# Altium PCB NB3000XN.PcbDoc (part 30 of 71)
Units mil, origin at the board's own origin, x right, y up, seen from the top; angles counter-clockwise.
Board outline 9527.56 x 6929.77 mil, 6 copper layers (Top Layer, GND+SHIELD, MidLayer1, MidLayer2, P2 - 3V3+5V0, Bottom Layer), stack 62.375 mil thick; 832 components, 1027 nets, 4655 pads, 4981 vias.
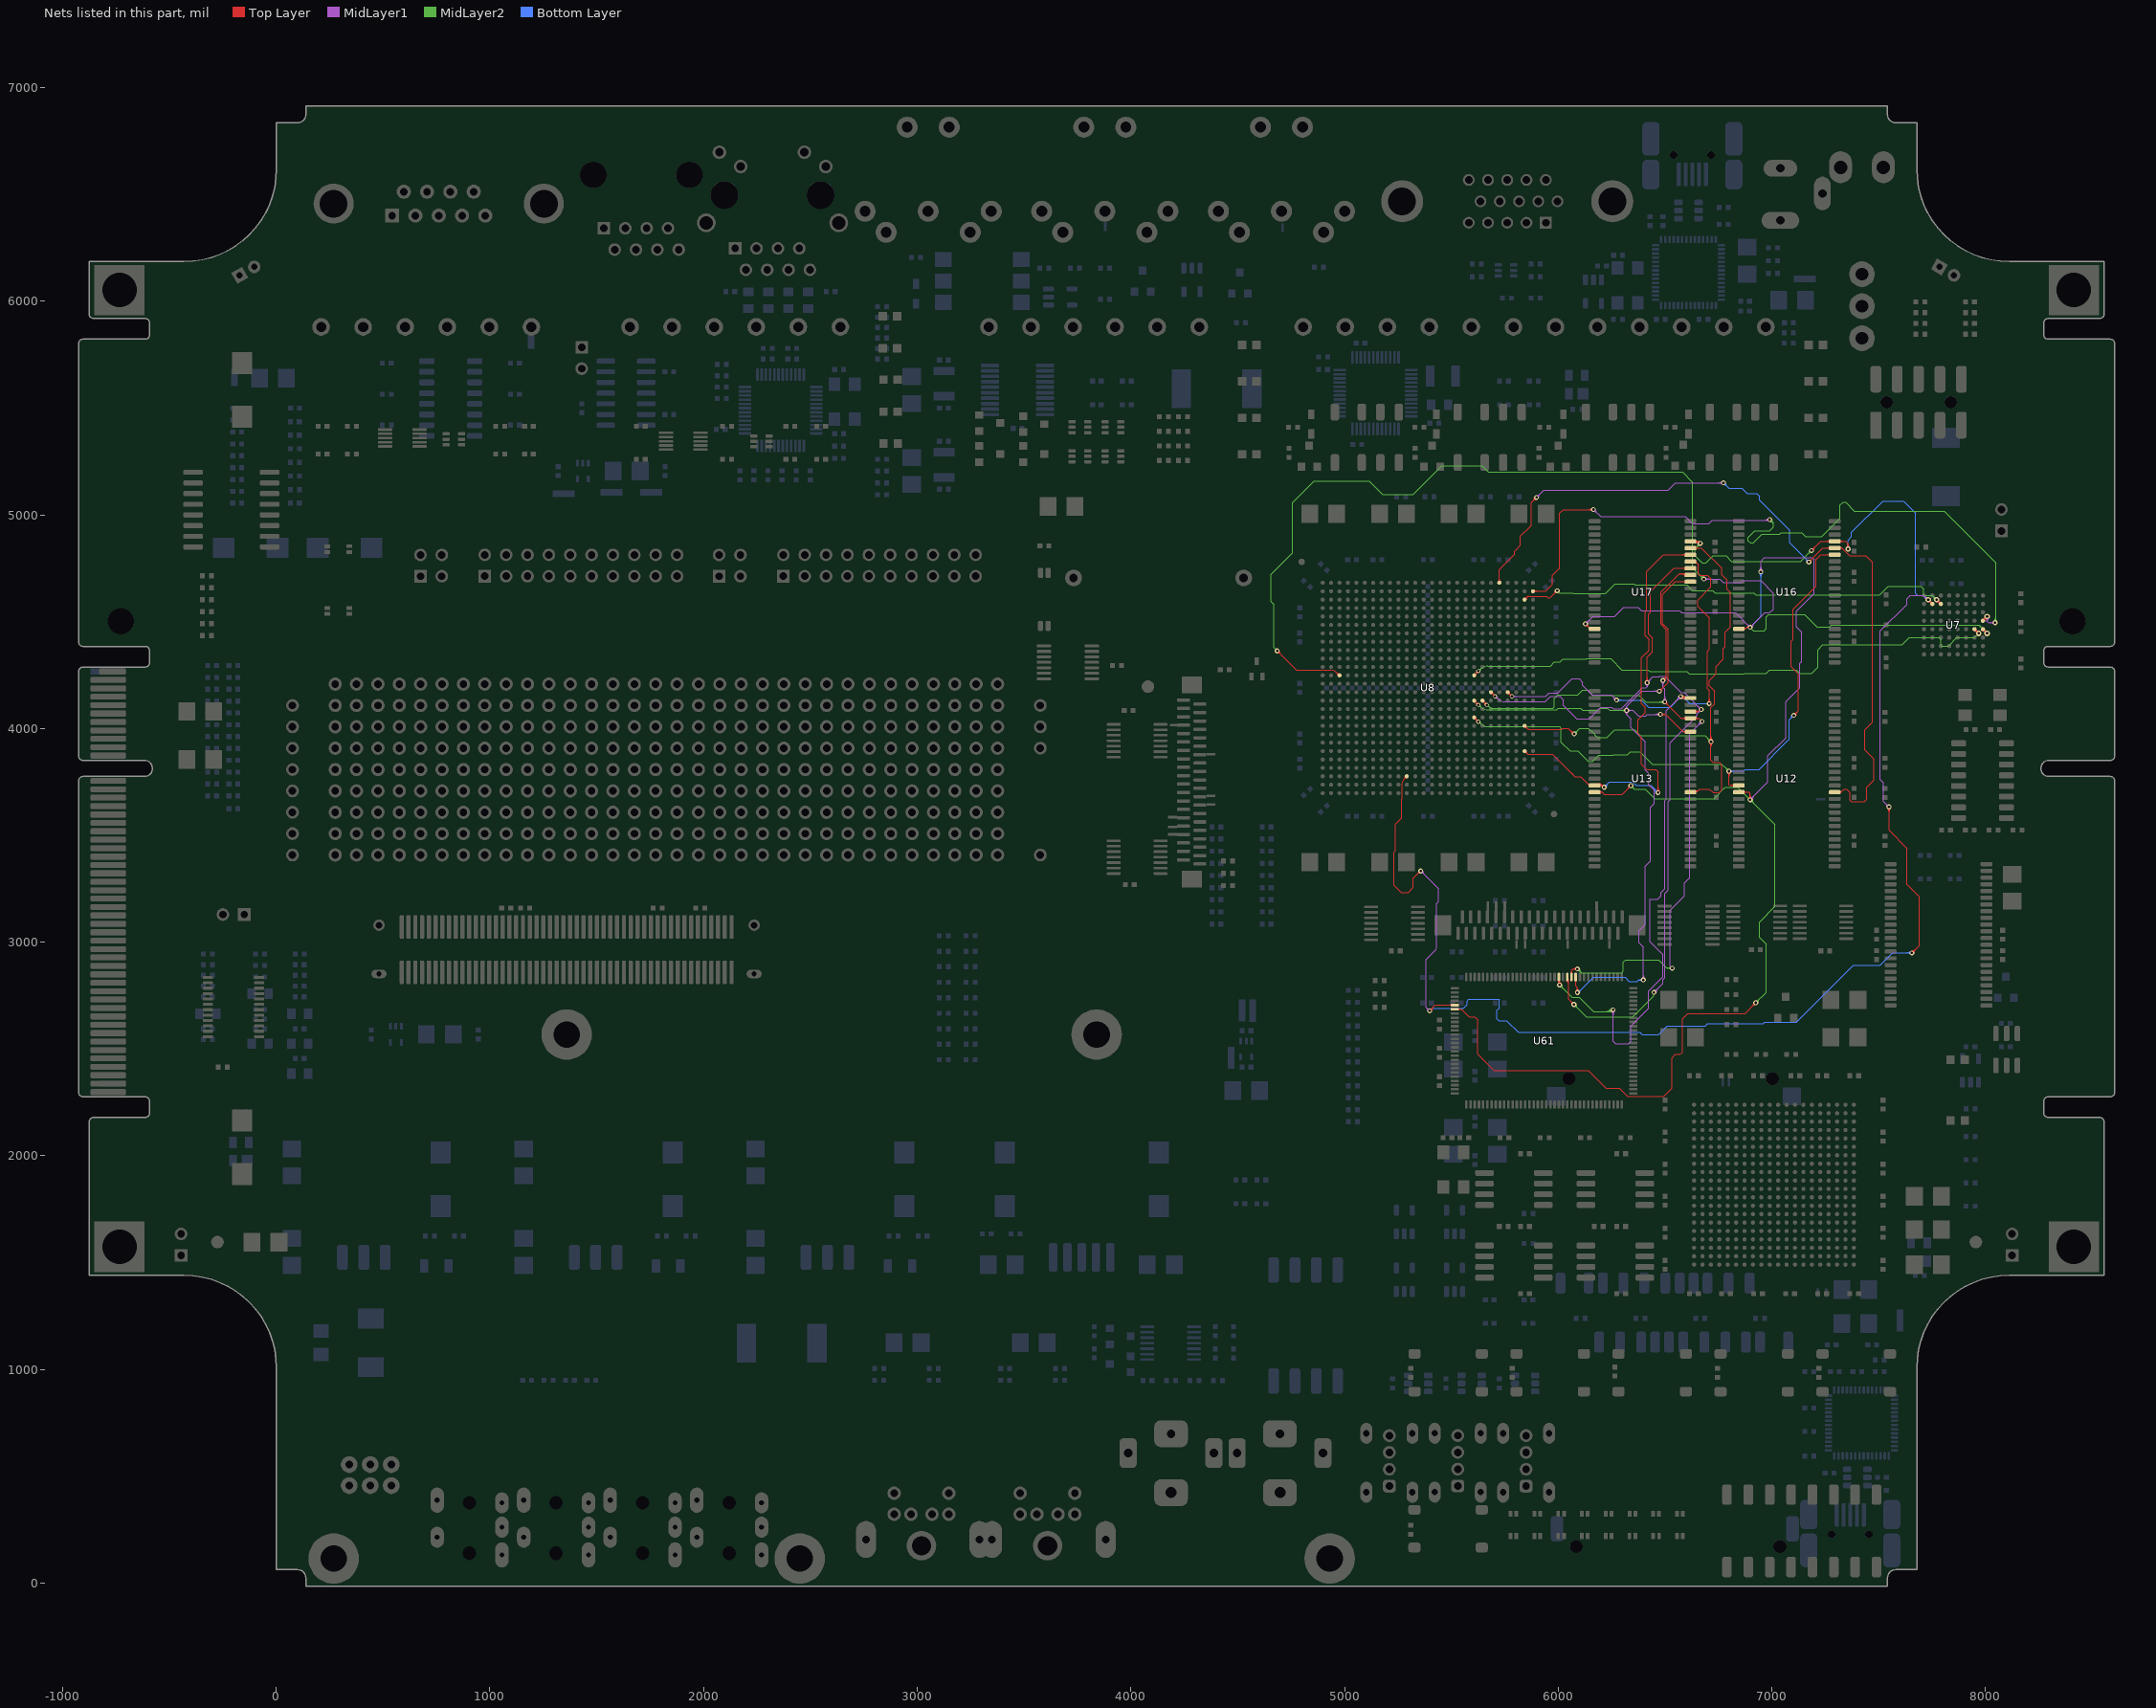
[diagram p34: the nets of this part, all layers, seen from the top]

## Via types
v1: diameter 23, hole 11.81, Top Layer to Bottom Layer, 3672 vias
v2: diameter 26, hole 11.81, Top Layer to Bottom Layer, 461 vias
v3: diameter 19, hole 11.81, Top Layer to Bottom Layer, tented both sides, 396 vias
v4: diameter 23.62, hole 11.81, Top Layer to Bottom Layer, 288 vias
v5: diameter 20, hole 11.81, Top Layer to Bottom Layer, 91 vias
v6: diameter 23, hole 11.81, Top Layer to Bottom Layer, tented both sides, 50 vias
v7: diameter 31, hole 11.81, Top Layer to Bottom Layer, 15 vias
v8: diameter 27.56, hole 11.81, Top Layer to Bottom Layer, tented both sides, 4 vias
v9: diameter 29, hole 11.81, Top Layer to Bottom Layer, 3 vias
v10: diameter 21, hole 11.81, Top Layer to Bottom Layer, 1 vias

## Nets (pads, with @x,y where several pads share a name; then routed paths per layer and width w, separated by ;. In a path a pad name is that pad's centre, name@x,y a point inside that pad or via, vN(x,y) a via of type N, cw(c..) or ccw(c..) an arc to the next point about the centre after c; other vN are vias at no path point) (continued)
DB_MEM.BUS_D28: U8.R19 U13.48 U17.35 U61.76 | length 4548
  Top Layer w4: U8.R19@5606.54,4123.44 cw(c5606.54,4105.34) 5619.34,4118.14 cw(c5632.14,4130.94) U8.R19@5614.04,4130.94 ; U8.R19@5606.54,4123.6 cw(c5606.54,4105.88) 5619.07,4118.41 cw(c5631.6,4130.94) U8.R19@5613.88,4130.94 ; U8.R19@5606.54,4130.94 v3(5626.22,4111.26) ; U61.76@6078.98,2821.32 cw(c6072.15,2814.49) 6081.81,2814.49 cw(c6091.47,2814.49) U61.76@6084.64,2821.32 ; U61.76@6081.81,2837.34 6081.81,2795 6090.19,2786.62 ; v1@6083.7,2771.64 ccw(c6069.67,2786.62) 6090.19,2786.62 ; v1@6086.43,2768.72 ccw(c6078.31,2777.39) 6090.19,2777.39 ccw(c6102.07,2777.39) v1@6093.95,2768.72 ; v1(6090.19,2764.71) 6090.19,2786.62 ; v1@6096.68,2771.64 cw(c6110.71,2786.62) 6090.19,2786.62 ; v1(6473.52,4175.04) 6515.19,4216.71 6515.19,4465.37 6488.86,4491.71 6488.86,4627.58 6548.52,4687.24 U17.35@6619.41,4687.24 ; v1@6473.52,4180.54 ccw(c6473.52,4193.82) 6482.91,4184.43 ccw(c6492.3,4175.04) v1@6479.02,4175.04 ; v1@6473.52,4184.54 ccw(c6473.52,4207.48) 6489.74,4191.26 ccw(c6505.96,4175.04) v1@6483.02,4175.04 ; v1(6478.52,4066.71) 6503.29,4066.71 6584.53,3985.47 ; v1@6482.41,4062.82 cw(c6491.8,4053.43) 6491.8,4066.71 cw(c6491.8,4079.99) v1@6482.41,4070.6 ; v1@6485.24,4059.99 cw(c6501.46,4043.77) 6501.46,4066.71 cw(c6501.46,4089.64) v1@6485.24,4073.43 ; U13.48@6595.76,3980.29 ccw(c6584.53,3970.72) 6584.53,3985.47 ; U13.48@6595.76,3990.66 cw(c6584.53,4000.23) 6584.53,3985.47 ; U17.35@6596.19,4681.59 ccw(c6582.54,4667.93) 6582.54,4687.24 ccw(c6582.54,4706.56) U17.35@6596.19,4692.9 ; U13.48@6619.41,3985.47 6584.53,3985.47 ; 5613.42,4124.06 cw(c5600.61,4111.26) 5618.72,4111.26 ccw(c5600.61,4111.26) 5613.42,4124.06 ; 5613.42,4124.06 ccw(c5626.22,4136.87) 5626.22,4118.76 cw(c5626.22,4136.87) 5613.42,4124.06
  MidLayer1 w4: v4@6314,4077.24 cw(c6304.52,4065) 6320,4065 ; v4@6314.24,4092.94 ccw(c6306.04,4104.24) 6320,4104.24 ; v4@6316.44,4080.4 cw(c6310.83,4073.15) 6320,4073.15 cw(c6329.17,4073.15) v4@6323.56,4080.4 ; v4@6324.11,4080.89 cw(c6334.03,4070.97) 6334.03,4085 cw(c6334.03,4099.03) v4@6324.11,4089.11 ; v4@6325.76,4092.94 cw(c6333.96,4104.24) 6320,4104.24 ; v4@6326,4077.24 ccw(c6335.48,4065) 6320,4065 ; v4@6326.94,4078.06 cw(c6343.69,4061.31) 6343.69,4085 cw(c6343.69,4108.69) v4@6326.94,4091.94 ; v1@6391.81,2830.09 ccw(c6375.59,2846.31) 6398.52,2846.31 ccw(c6421.46,2846.31) v1@6405.24,2830.09 ; v1@6394.64,2827.26 ccw(c6385.25,2836.65) 6398.52,2836.65 ccw(c6411.8,2836.65) v1@6402.41,2827.26 ; v1(6398.52,2823.37) 6398.52,2978.02 6379.19,2997.35 6379.19,3054.08 6406.86,3081.75 6406.86,3356.39 6431.86,3381.39 6431.86,3631.06 6449.19,3648.39 6449.19,3711.35 6423.52,3737.02 6423.52,3789.35 6406.86,3806.02 6406.86,3937.69 6340,4004.54 6340,4045 6320,4065 ; v1@6466.81,4168.32 ccw(c6450.59,4152.11) 6450.59,4175.04 ccw(c6450.59,4197.98) v1@6466.81,4181.76 ; v1@6469.64,4171.15 ccw(c6460.25,4161.76) 6460.25,4175.04 ccw(c6460.25,4188.32) v1@6469.64,4178.93 ; v1@6471.81,4059.99 ccw(c6455.59,4043.77) 6455.59,4066.71 ccw(c6455.59,4089.64) v1@6471.81,4073.43 ; v1(6473.52,4175.04) 6390.8,4175.04 6320,4104.24 ; v1@6474.64,4062.82 ccw(c6465.25,4053.43) 6465.25,4066.71 ccw(c6465.25,4079.99) v1@6474.64,4070.6 ; v1(6478.52,4066.71) 6416.71,4066.71 6410,4060 6375,4060 6350,4085 v4(6320,4085) ; 6320,4065 v4(6320,4085) ; v4(6320,4085) 6320,4104.24
  MidLayer2 w4: v3@5626.87,4103.79 cw(c5628.45,4085.75) 5640.09,4099.62 ; v3@5633.69,4111.91 ccw(c5651.73,4113.49) 5640.09,4099.62 ; v4@6313.06,4078.06 ccw(c6296.31,4061.31) 6296.31,4085 ccw(c6296.31,4108.69) v4@6313.06,4091.94 ; v4@6315.89,4080.89 ccw(c6305.97,4070.97) 6305.97,4085 ccw(c6305.97,4099.03) v4@6315.89,4089.11 ; v4(6320,4085) 6242.25,4085 6231.54,4095.71 6195.71,4095.71 6185,4085 6115,4085 6105,4095 6000,4095 5992.4,4087.4 5920,4087.4 5910,4087.4 5782.64,4087.4 5763.22,4087.4 5689.1,4087.4 5669.6,4087.4 cw(c5669.6,4129.13) 5640.09,4099.62
  Bottom Layer w4: v1(6090.19,2764.71) 6094.86,2764.71 6166.19,2836.04 6312.52,2836.04 6331.86,2816.71 6370,2816.71 6376.67,2823.37 ; v1@6090.19,2766.21 ccw(c6090.19,2781.1) 6100.72,2770.57 ; v1@6090.19,2770.21 ccw(c6090.19,2794.75) 6107.55,2777.4 ; v1@6090.19,2774.21 ccw(c6090.19,2808.41) 6114.37,2784.23 ; v1@6099.69,2764.71 cw(c6111.36,2764.71) 6103.11,2772.96 ; v1@6391.58,2816.89 ccw(c6376.67,2802.98) 6376.67,2823.37 ; v1@6391.58,2829.86 cw(c6376.67,2843.77) 6376.67,2823.37 ; v1@6394.5,2819.62 ccw(c6385.87,2811.57) 6385.87,2823.37 ccw(c6385.87,2835.18) v1@6394.5,2827.13 ; v1(6398.52,2823.37) 6376.67,2823.37
DB_MEM.BUS_D29: U8.R20 U13.50 U17.36 U61.77 | length 4450
  Top Layer w4: U8.R20@5645.91,4123.44 cw(c5645.91,4105.34) 5658.71,4118.14 cw(c5671.51,4130.94) U8.R20@5653.41,4130.94 ; U8.R20@5645.91,4123.6 cw(c5645.91,4105.88) 5658.44,4118.41 cw(c5670.97,4130.94) U8.R20@5653.25,4130.94 ; U8.R20@5645.91,4130.94 v3(5665.59,4111.26) ; U61.77@6059.3,2853.36 ccw(c6052.47,2860.19) 6062.13,2860.19 ccw(c6071.78,2860.19) U61.77@6064.95,2853.36 ; U61.77@6062.12,2837.34 6062.13,2867.04 6070.13,2875.04 ; v1@6082.84,2869.02 ccw(c6070.13,2858.6) 6070.13,2875.04 ; v1@6082.84,2881.06 cw(c6070.13,2891.48) 6070.13,2875.04 ; v1@6085.94,2871.56 ccw(c6078.57,2865.52) 6078.57,2875.04 ccw(c6078.57,2884.56) v1@6085.94,2878.53 ; v1(6090.19,2875.04) 6070.13,2875.04 ; v1(6490.19,4225.04) 6506.86,4241.71 6506.86,4462.39 6480.52,4488.73 6480.52,4639.37 6566.19,4725.04 6601.84,4725.04 6601.84,4718.74 U17.36@6619.41,4718.74 ; v1@6490.19,4230.54 ccw(c6490.19,4243.82) 6499.58,4234.43 ccw(c6508.97,4225.04) v1@6495.69,4225.04 ; v1@6490.19,4234.54 ccw(c6490.19,4257.48) 6506.41,4241.26 ccw(c6522.63,4225.04) v1@6499.69,4225.04 ; v1@6498.52,4115.54 cw(c6498.52,4092.61) 6514.74,4108.82 cw(c6530.96,4125.04) v1@6508.02,4125.04 ; v1@6498.52,4119.54 cw(c6498.52,4106.26) 6507.91,4115.65 cw(c6517.3,4125.04) v1@6504.02,4125.04 ; v1(6498.52,4125.04) 6575.1,4048.46 U13.50@6619.41,4048.46 6658.44,4048.46 v1(6673.52,4033.37) ; 6567.33,4725.04 cw(c6567.33,4684.21) U17.36@6596.19,4713.08 ; 6576.98,4725.04 cw(c6576.98,4693.87) U17.36@6599.02,4715.91 ; 6586.64,4725.04 cw(c6586.64,4703.53) U17.36@6601.85,4718.74 ; U13.50@6596.19,4042.81 ccw(c6582.54,4029.15) 6582.54,4048.46 ccw(c6582.54,4067.78) U13.50@6596.19,4054.12 ; U13.50@6642.63,4042.81 cw(c6656.28,4029.15) 6656.28,4048.46 cw(c6656.28,4067.78) U13.50@6642.63,4054.12 ; 5652.79,4124.06 cw(c5639.98,4111.26) 5658.09,4111.26 ccw(c5639.98,4111.26) 5652.79,4124.06 ; 5652.79,4124.06 ccw(c5665.59,4136.87) 5665.59,4118.76 cw(c5665.59,4136.87) 5652.79,4124.06
  MidLayer1 w4: v1@6483.47,4218.32 cw(c6467.26,4202.11) 6490.19,4202.11 cw(c6513.13,4202.11) v1@6496.91,4218.32 ; v1@6486.3,4221.15 cw(c6476.91,4211.76) 6490.19,4211.76 cw(c6503.47,4211.76) v1@6494.08,4221.15 ; v1(6490.19,4225.04) 6490.19,4193.33 6498.52,4185 v1(6498.52,4125.04) ; v1@6491.81,4131.76 ccw(c6475.59,4147.98) 6498.52,4147.98 ccw(c6521.46,4147.98) v1@6505.24,4131.76 ; v1@6494.64,4128.93 ccw(c6485.25,4138.32) 6498.52,4138.32 ccw(c6511.8,4138.32) v1@6502.41,4128.93 ; v1(6533.86,2878.37) 6523.52,2888.71 6523.52,3150.04 6590.19,3216.71 6590.19,3277.04 6615.19,3302.04 6615.19,3975.04 v1(6673.52,4033.37) ; v1@6664.02,4033.37 cw(c6641.09,4033.37) 6657.31,4017.16 cw(c6673.52,4000.94) v1@6673.52,4023.87 ; v1@6668.02,4033.37 cw(c6654.75,4033.37) 6664.14,4023.99 cw(c6673.52,4014.6) v1@6673.52,4027.87
  MidLayer2 w4: v3@5666.24,4103.79 cw(c5667.82,4085.75) 5679.46,4099.62 cw(c5691.1,4113.49) v3@5673.06,4111.91 ; 5679.17,4099.87 ccw(c5689.1,4109.8) 5689.1,4095.75 5782.64,4095.75 5910,4095.75 5920,4095.75 5975.75,4095.75 5981.86,4101.86 5981.86,4141.71 5998.52,4158.37 6092.54,4158.37 6114.17,4180 6139.56,4180 6163.19,4156.37 6320,4156.37 6378.54,4156.37 6409.88,4125.04 v1(6498.52,4125.04) ; v1@6090.19,2865.54 cw(c6090.19,2842.61) 6106.41,2858.82 cw(c6122.63,2875.04) v1@6099.69,2875.04 ; v1@6090.19,2869.54 cw(c6090.19,2856.26) 6099.58,2865.65 cw(c6108.97,2875.04) v1@6095.69,2875.04 ; v1@6090.23,2875 v1(6090.19,2875.04) 6107.86,2857.37 6297,2857.37 6305,2865.37 6305,2907.71 6315,2917.71 6470,2917.71 6509.33,2878.37 v1(6533.86,2878.37) ; v1@6491.81,4118.32 ccw(c6475.59,4102.11) 6475.59,4125.04 ccw(c6475.59,4147.98) v1@6491.81,4131.76 ; v1@6494.64,4121.15 ccw(c6485.25,4111.76) 6485.25,4125.04 ccw(c6485.25,4138.32) v1@6494.64,4128.93 ; v1@6527.14,2871.66 ccw(c6510.92,2855.44) 6510.92,2878.37 ccw(c6510.92,2901.31) v1@6527.14,2885.09 ; v1@6529.97,2874.49 ccw(c6520.58,2865.1) 6520.58,2878.37 ccw(c6520.58,2891.65) v1@6529.97,2882.26
DB_MEM.BUS_D30: U8.P21 U13.51 U17.37 U61.78 | length 4758.4
  Top Layer w4: U8.P21@5685.28,4162.81 cw(c5685.28,4144.71) 5698.08,4157.51 cw(c5710.88,4170.31) U8.P21@5692.78,4170.31 ; U8.P21@5685.28,4162.97 cw(c5685.28,4145.25) 5697.81,4157.78 cw(c5710.34,4170.31) U8.P21@5692.62,4170.31 ; U8.P21@5685.28,4170.31 v3(5704.96,4150.63) ; U61.78@6039.61,2821.32 cw(c6018.09,2799.8) 6048.52,2799.8 ; U61.78@6042.44,2824.14 cw(c6027.75,2809.46) 6048.52,2809.46 ; U61.78@6045.27,2826.97 cw(c6037.41,2819.11) 6048.52,2819.11 ; U61.78@6048.1,2829.8 cw(c6047.07,2828.77) 6048.52,2828.77 ; 6048.52,2827.29 6048.52,2733.37 v1(6073.52,2708.37) ; v1@6064.02,2708.37 ccw(c6041.09,2708.37) 6057.31,2724.59 ccw(c6073.52,2740.81) v1@6073.52,2717.87 ; v1@6068.02,2708.37 ccw(c6054.75,2708.37) 6064.14,2717.76 ccw(c6073.52,2727.15) v1@6073.52,2713.87 ; v1(6416.19,4214.37) 6416.19,4334.69 6441.52,4360.02 6441.52,4423.71 6423.52,4441.71 6423.52,4536.37 6431.86,4544.71 6431.86,4640.71 6541.19,4750.04 6619.41,4750.04 6623.52,4750.04 6623.52,4750.24 U17.37@6619.41,4750.24 ; 6582.07,4750.04 ccw(c6582.07,4770.02) U17.37@6596.19,4755.89 ; 6583.01,4750.04 cw(c6583.01,4731.39) U17.37@6596.19,4744.58 ; 6591.72,4750.04 ccw(c6591.72,4760.36) U17.37@6599.02,4753.06 ; U13.51@6619.41,4079.96 6653.44,4079.96 ; U13.51@6643.26,4075.01 cw(c6653.44,4067) 6653.44,4079.96 ; U13.51@6643.26,4084.91 ccw(c6653.44,4092.92) 6653.44,4079.96 ; 6654.1,4080.62 cw(c6663.8,4070.92) v1@6668.36,4083.85 ; 6658.59,4085.11 cw(c6666.14,4077.56) v1@6669.69,4087.63 ; v1(6670.19,4089.04) 6662.52,4089.04 6653.44,4079.96 ; 5692.16,4163.43 cw(c5679.35,4150.63) 5697.46,4150.63 ccw(c5679.35,4150.63) 5692.16,4163.43 ; 5692.16,4163.43 ccw(c5704.96,4176.24) 5704.96,4158.13 cw(c5704.96,4176.24) 5692.16,4163.43 ; 6416.19,4227.65 cw(c6402.91,4227.65) 6412.3,4218.26 ccw(c6402.91,4227.65) 6416.19,4227.65 ; 6416.19,4227.65 ccw(c6429.47,4227.65) 6420.08,4218.26 cw(c6429.47,4227.65) 6416.19,4227.65 ; 6416.19,4237.31 cw(c6393.26,4237.31) 6409.47,4221.09 ccw(c6393.26,4237.31) 6416.19,4237.31 ; 6416.19,4237.31 ccw(c6439.13,4237.31) 6422.91,4221.09 cw(c6439.13,4237.31) 6416.19,4237.31
  MidLayer1 w4: v3@5705.61,4143.16 cw(c5707.19,4125.12) 5718.83,4138.99 ; v3@5712.43,4151.28 ccw(c5730.47,4152.86) 5718.83,4138.99 ; 5781.77,4126.77 5767.84,4126.77 ; v1@6416.19,4219.87 ccw(c6416.19,4233.15) 6425.58,4223.76 ccw(c6434.97,4214.37) v1@6421.69,4214.37 ; v1@6416.19,4223.87 ccw(c6416.19,4246.81) 6432.41,4230.59 ccw(c6448.63,4214.37) v1@6425.69,4214.37 ; v1(6448.52,2765.37) 6490.19,2807.04 6490.19,2825.65 6499.19,2834.65 6499.19,3227.73 6515.19,3243.73 6515.19,3657.77 6523.52,3666.1 6523.52,3933.34 6650,4059.81 6650,4068.85 v1(6670.19,4089.04) 6591.52,4167.71 6575.86,4167.71 6498.52,4245.04 6475,4245.04 6472,4242.04 6443.86,4242.04 v1(6416.19,4214.37) 6416.19,4196.04 ; v1@6448.52,2770.87 ccw(c6448.52,2784.15) 6457.91,2774.76 ccw(c6467.3,2765.37) v1@6454.02,2765.37 ; v1@6448.52,2774.87 ccw(c6448.52,2797.81) 6464.74,2781.59 ccw(c6480.96,2765.37) v1@6458.02,2765.37 ; v1@6670.19,4079.54 ccw(c6670.19,4056.61) 6653.97,4072.82 ccw(c6637.76,4089.04) 6660.69,4089.04 ccw(c6637.76,4089.04) 6653.97,4105.26 ccw(c6670.19,4121.48) v1@6670.19,4098.54 ; v1@6670.19,4083.54 ccw(c6670.19,4070.26) 6660.8,4079.65 ccw(c6651.41,4089.04) 6664.69,4089.04 ccw(c6651.41,4089.04) 6660.8,4098.43 ccw(c6670.19,4107.82) v1@6670.19,4094.54 ; 5718.83,4138.99 ccw(c5748.34,4168.5) 5748.34,4126.77 5767.84,4126.77 ; 5767.84,4126.77 5841.96,4126.77 5861.38,4126.77 5910,4126.77 5920,4126.77 5924.74,4126.77 5940.25,4126.77 5963.52,4150.04 6008.52,4150.04 6025.52,4133.04 6025.52,4108.04 6087.69,4045.87 6144.36,4045.87 6198.52,4100.04 6250.9,4100.04 6259.23,4091.71 6296.15,4091.71 6394.62,4190.18 6410.33,4190.18 6416.19,4196.04 ; 6416.19,4196.04 cw(c6429.13,4196.04) 6421.67,4206.61 ccw(c6429.13,4196.04) 6416.19,4196.04 ; 6416.19,4196.04 ccw(c6403.25,4196.04) 6410.71,4206.61 cw(c6403.25,4196.04) 6416.19,4196.04
  MidLayer2 w4: v1@6073.52,2698.87 cw(c6073.52,2675.94) 6089.74,2692.16 cw(c6105.96,2708.37) v1@6083.02,2708.37 ; v1@6073.52,2702.87 cw(c6073.52,2689.6) 6082.91,2698.99 cw(c6092.3,2708.37) v1@6079.02,2708.37 ; v1(6073.52,2708.37) 6131.86,2650.04 6348.52,2650.04 6448.52,2750.04 v1(6448.52,2765.37)
DB_MEM.BUS_D31: U8.P23 U13.53 U17.38 U61.80 | length 5350.7
  Top Layer w4: U8.P23@5764.02,4162.81 cw(c5764.02,4144.71) 5776.82,4157.51 cw(c5789.62,4170.31) U8.P23@5771.52,4170.31 ; U8.P23@5764.02,4162.97 cw(c5764.02,4145.25) 5776.55,4157.78 cw(c5789.08,4170.31) U8.P23@5771.36,4170.31 ; U8.P23@5764.02,4170.31 v3(5783.7,4150.63) ; v1@6000.14,2806.43 ccw(c5993.06,2813.5) 6003.07,2813.5 ; U61.80@6000.24,2821.32 cw(c5993.41,2814.49) 6003.07,2814.49 cw(c6012.73,2814.49) U61.80@6005.9,2821.32 ; 6003.07,2812.47 ccw(c6019.62,2812.47) v1@6007.92,2800.77 ; U61.80@6003.07,2822.13 ccw(c6029.28,2822.13) v1@6010.75,2803.6 ; U61.80@6003.07,2831.79 ccw(c6038.93,2831.79) v1@6013.57,2806.43 ; U61.80@6003.07,2837.34 6003.07,2810.83 6006.86,2807.04 v1(6006.86,2799.71) ; v1@6571.76,4148.27 ccw(c6584.6,4161.12) 6584.6,4142.95 ; v1(6573.52,4150.04) 6573.52,4143.37 6575.19,4141.71 6581.86,4141.71 6583.1,4142.95 ; v1@6574.58,4151.1 ccw(c6594.26,4170.77) U13.53@6594.26,4142.95 ; v1@6577.41,4153.93 ccw(c6603.91,4180.43) U13.53@6603.91,4142.95 ; v1@6580.24,4156.76 ccw(c6613.57,4190.09) U13.53@6613.57,4142.95 ; U13.53@6596.07,4137.42 ccw(c6583.1,4124.99) 6583.1,4142.95 ; U13.53@6596.07,4148.49 cw(c6583.1,4160.92) 6583.1,4142.95 ; U13.53@6619.41,4142.95 6583.1,4142.95 ; U17.38@6619.41,4781.73 6631.86,4781.73 6631.86,4775.04 6648.52,4775.04 6656.86,4766.71 6656.86,4722.37 6661.52,4717.71 6698.52,4717.71 6715.19,4701.04 6715.19,4662.71 6653.86,4601.37 6653.86,4570.96 6706.86,4517.96 6706.86,4369.35 6698.52,4361.02 6698.52,4185.71 6706.86,4177.37 v1(6706.86,4116.71) ; U17.38@6636.97,4777.73 cw(c6636.97,4756.33) 6652.1,4771.46 ; U17.38@6640.35,4774.48 cw(c6644.31,4765.97) 6650.96,4772.61 ; v1@6700.14,4123.43 ccw(c6683.92,4139.64) 6706.86,4139.64 ccw(c6729.79,4139.64) v1@6713.57,4123.43 ; v1@6702.97,4120.6 ccw(c6693.58,4129.99) 6706.86,4129.99 ccw(c6720.14,4129.99) v1@6710.75,4120.6 ; 5770.9,4163.43 cw(c5758.09,4150.63) 5776.2,4150.63 ccw(c5758.09,4150.63) 5770.9,4163.43 ; 5770.9,4163.43 ccw(c5783.7,4176.24) 5783.7,4158.13 cw(c5783.7,4176.24) 5770.9,4163.43 ; U17.38@6644.97,4781.73 ccw(c6652.54,4781.73) 6647.19,4776.38 cw(c6652.54,4781.73) U17.38@6644.97,4781.73
  MidLayer1 w4: v3(5783.7,4150.63) 5861.38,4150.63 5910,4150.63 5920,4150.63 5941.05,4150.63 5957.13,4166.71 5998.52,4166.71 6065.19,4233.37 6098.52,4233.37 6115.19,4216.71 6115.19,4201.37 6158.19,4158.37 6248.52,4158.37 v1(6273.52,4133.37) ; v3@5788.89,4145.44 cw(c5801.43,4132.9) 5801.43,4150.63 cw(c5801.43,4168.36) v3@5788.89,4155.82 ; v1@6250.14,2676.66 cw(c6233.92,2660.44) 6256.86,2660.44 cw(c6279.79,2660.44) v1@6263.57,2676.66 ; v1@6252.97,2679.49 cw(c6243.58,2670.1) 6256.86,2670.1 cw(c6270.14,2670.1) v1@6260.75,2679.49 ; v1(6256.86,2683.37) 6256.86,2535.69 6267.51,2525.04 6328.88,2525.04 6340.19,2536.35 6340.19,2608.37 6423.52,2691.71 6423.52,2770.3 6491.19,2837.96 6491.19,2940.71 6430.86,3001.04 6430.86,3200.37 6431.86,3201.37 6465.19,3201.37 6481.86,3218.04 6481.86,3233.02 6498.52,3249.69 6498.52,3663.73 6506.86,3672.06 6506.86,4083.37 v1(6573.52,4150.04) ; v1@6264.02,4133.37 ccw(c6241.09,4133.37) 6257.31,4149.59 ccw(c6273.52,4165.81) v1@6273.52,4142.87 ; v1@6268.02,4133.37 ccw(c6254.75,4133.37) 6264.14,4142.76 ccw(c6273.52,4152.15) v1@6273.52,4138.87 ; v1@6564.02,4150.04 cw(c6541.09,4150.04) 6557.31,4133.82 cw(c6573.52,4117.61) v1@6573.52,4140.54 ; v1@6568.02,4150.04 cw(c6554.75,4150.04) 6564.14,4140.65 cw(c6573.52,4131.26) v1@6573.52,4144.54 ; 5801.81,4150.63 cw(c5801.81,4168.74) 5789,4155.93 ccw(c5801.81,4168.74) 5801.81,4150.63 ; 5801.81,4150.63 ccw(c5801.81,4132.52) 5789,4145.33 cw(c5801.81,4132.52) 5801.81,4150.63
  MidLayer2 w4: v1@6006.86,2790.21 cw(c6006.86,2767.27) 6023.07,2783.49 cw(c6039.29,2799.71) v1@6016.36,2799.71 ; v1@6006.86,2794.21 cw(c6006.86,2780.93) 6016.25,2790.32 cw(c6025.64,2799.71) v1@6012.36,2799.71 ; v1(6006.86,2799.71) 6064.86,2741.71 6099.52,2741.71 6166.19,2675.04 6248.52,2675.04 v1(6256.86,2683.37) ; 6213.8,2675.04 ccw(c6213.8,2726.43) v1@6250.14,2690.09 ; 6223.46,2675.04 ccw(c6223.46,2716.77) v1@6252.97,2687.26 ; 6233.12,2675.04 ccw(c6233.12,2707.12) v1@6255.8,2684.44 ; 6242.77,2675.04 ccw(c6242.77,2697.46) v1@6258.62,2681.61
  Bottom Layer w4: v1(6273.52,4133.37) 6390.19,4133.37 6423.52,4100.04 6523.52,4100.04 v1(6573.52,4150.04) 6582.52,4150.04 6615.86,4116.71 v1(6706.86,4116.71) ; v1@6277.41,4129.49 cw(c6286.8,4120.1) 6286.8,4133.37 cw(c6286.8,4146.65) v1@6277.41,4137.26 ; v1@6280.24,4126.66 cw(c6296.46,4110.44) 6296.46,4133.37 cw(c6296.46,4156.31) v1@6280.24,4140.09 ; v1@6564.02,4150.04 cw(c6541.09,4150.04) 6557.31,4133.82 cw(c6573.52,4117.61) 6573.52,4140.54 cw(c6573.52,4095.88) 6605.11,4127.46 ; v1@6568.02,4150.04 cw(c6554.75,4150.04) 6564.14,4140.65 cw(c6573.52,4131.26) 6573.52,4144.54 cw(c6573.52,4109.53) 6598.28,4134.29 ; v1@6573.52,4148.54 cw(c6573.52,4123.19) 6591.45,4141.12
DB_MEM.BUS_FLASH_NBUSY: U7.A4 U8.B26 | length 3978.1
  Top Layer w4: U8.B26@5882.13,4642.76 5910,4642.76 5920,4642.76 5924.74,4642.76 5941.24,4642.76 5973.52,4675.04 5973.52,4716.71 6006.86,4750.04 6006.86,5008.37 6023.52,5025.04 v1(6165.19,5025.04) ; U8.B26@5887.32,4637.56 cw(c5899.85,4625.03) 5899.85,4642.76 cw(c5899.85,4660.48) U8.B26@5887.32,4647.95 ; U8.B26@5887.43,4637.45 cw(c5900.23,4624.65) 5900.23,4642.76 cw(c5900.23,4660.86) U8.B26@5887.43,4648.06 ; v1@6158.47,5018.32 ccw(c6142.26,5002.11) 6142.26,5025.04 ccw(c6142.26,5047.98) v1@6158.47,5031.76 ; v1@6161.3,5021.15 ccw(c6151.91,5011.76) 6151.91,5025.04 ccw(c6151.91,5038.32) v1@6161.3,5028.93
  Top Layer w8: U7.A4@7987.8,4504.68 v2(8007.48,4524.37) ; U7.A4@7987.8,4510.68 ccw(c7987.8,4525.17) 7998.04,4514.93 ccw(c8008.28,4504.68) U7.A4@7993.8,4504.68 ; v2@7998.48,4524.37 cw(c7976.75,4524.37) 7992.12,4509.01 cw(c8007.48,4493.64) v2@8007.48,4515.37
  MidLayer1 w4: v1@6165.19,5015.54 cw(c6165.19,4992.61) 6181.41,5008.82 cw(c6197.63,5025.04) v1@6174.69,5025.04 ; v1@6165.19,5019.54 cw(c6165.19,5006.26) 6174.58,5015.65 cw(c6183.97,5025.04) v1@6170.69,5025.04 ; v1(6165.19,5025.04) 6198.52,4991.71 6595,4991.71 6626.71,4960 6704.96,4960 6720,4975.04 6988.52,4975.04 6990.19,4976.71 v1(6990.19,4978.04) ; 6960.01,4975.04 ccw(c6960.01,5008.22) v1@6983.47,4984.76 ; 6969.67,4975.04 ccw(c6969.67,4998.56) v1@6986.3,4981.93 ; 6974.5,4975.04 cw(c6974.5,4962.35) v1@6983.47,4971.32 ; v2@8000.93,4515.53 cw(c7991.28,4502.52) 8007.48,4502.52 ; v2@8003.31,4518.75 cw(c7997.17,4510.47) 8007.48,4510.47 cw(c8017.79,4510.47) v2@8011.65,4518.75 ; v2@8007.48,4525.04 8006.86,4525.04 8006.86,4524.37 v2(8007.48,4524.37) 8007.48,4502.52 ; v2@8014.03,4515.53 ccw(c8023.68,4502.52) 8007.48,4502.52 ; v1@8038.14,4488.66 ccw(c8021.92,4472.44) 8021.92,4495.37 ccw(c8021.92,4518.31) v1@8038.14,4502.09 ; v1@8040.97,4491.49 ccw(c8031.58,4482.1) 8031.58,4495.37 ccw(c8031.58,4508.65) v1@8040.97,4499.26 ; v1(8044.86,4495.37) 8014.63,4495.37 8007.48,4502.52
  MidLayer2 w4: v1@6990.19,4968.54 cw(c6990.19,4945.61) 7006.41,4961.82 cw(c7022.63,4978.04) v1@6999.69,4978.04 ; v1@6990.19,4972.54 cw(c6990.19,4959.26) 6999.58,4968.65 cw(c7008.97,4978.04) v1@6995.69,4978.04 ; v1(6990.19,4978.04) 7007.69,4960.54 7007.69,4942.79 6989.94,4925.04 6920.44,4925.04 6889.36,4893.96 6889.36,4879.46 6899.61,4869.21 6914.11,4869.21 6953.94,4909.04 7035.84,4909.04 7043.34,4916.54 7140.61,4916.54 7157.94,4899.21 7234.21,4899.21 7319.36,4984.36 7319.36,5045.62 7333.73,5060 7345,5060 7387,5018 7806.17,5018 8048.52,4775.65 8048.52,4491.71 v1(8044.86,4495.37) ; v1@8038.14,4502.09 ccw(c8013.07,4527.16) 8048.52,4527.16 ; v1@8040.97,4499.26 ccw(c8022.73,4517.51) 8048.52,4517.51 ; v1@8043.8,4496.44 ccw(c8032.38,4507.85) 8048.52,4507.85 ; 8048.52,4509.46 ccw(c8058.94,4509.46) v1@8051.57,4502.09
DB_MEM.BUS_FLASH_NCS: U7.F2 U8.C25 | length 2309.8
  Top Layer w4: v1@5985.69,4645.04 cw(c5962.76,4645.04) 5978.97,4628.82 cw(c5995.19,4612.61) v1@5995.19,4635.54 ; v1@5989.69,4645.04 cw(c5976.41,4645.04) 5985.8,4635.65 cw(c5995.19,4626.26) v1@5995.19,4639.54 ; v1(5995.19,4645.04) 5962.39,4612.24 5953,4612.24 5946.35,4618.89 5938.74,4618.89 5938,4618.89 5924.74,4618.89 5920,4618.89 5910,4618.89 5862.47,4618.89 ; 5855.29,4615.92 cw(c5862.47,4608.74) 5862.47,4618.89 ; 5855.29,4615.92 cw(c5862.47,4608.74) 5862.47,4618.89 ; 5855.29,4615.92 ccw(c5867.83,4603.39) 5850.1,4603.39 cw(c5867.83,4603.39) 5855.29,4615.92 ; 5855.29,4615.92 cw(c5842.76,4628.45) 5842.76,4610.73 ccw(c5842.76,4628.45) 5855.29,4615.92
  Top Layer w8: v2@7771.26,4594.11 cw(c7771.26,4572.38) 7786.62,4587.75 cw(c7801.99,4603.11) v2@7780.26,4603.11 ; v2(7771.26,4603.11) U7.F2@7790.95,4583.43 ; U7.F2@7784.95,4583.43 ccw(c7770.46,4583.43) 7780.7,4593.67 ccw(c7790.95,4603.91) U7.F2@7790.95,4589.43
  MidLayer2 w4: v1(5995.19,4645.04) 6005.19,4635.04 6069.52,4635.04 6072.52,4632.04 6222.19,4632.04 6266.19,4676.04 6356.86,4676.04 6361.19,4671.71 6601.86,4671.71 6627.86,4645.71 6723.52,4645.71 6734.52,4634.71 6915.19,4634.71 6924.19,4625.71 7504.54,4625.71 7545.54,4666.71 7697.52,4666.71 7711.52,4652.71 7711.52,4626.37 7715.52,4622.37 7752,4622.37 v2(7771.26,4603.11) ; v2@7760.26,4603.11 ccw(c7733.71,4603.11) 7752.48,4621.89 ccw(c7771.26,4640.67) v2@7771.26,4614.11 ; v2@7764.26,4603.11 ccw(c7747.36,4603.11) 7759.31,4615.06 ccw(c7771.26,4627.01) v2@7771.26,4610.11
DB_MEM.BUS_FLASH_NRESET: U7.B5 U8.M19 | length 2817.2
  Top Layer w4: U8.M19@5606.54,4249.06 v3(5626.22,4268.74) ; U8.M19@5606.54,4256.4 ccw(c5606.54,4274.12) 5619.07,4261.59 ccw(c5631.6,4249.06) U8.M19@5613.88,4249.06 ; U8.M19@5606.54,4256.56 ccw(c5606.54,4274.66) 5619.34,4261.86 ccw(c5632.14,4249.06) U8.M19@5614.04,4249.06 ; 5613.42,4255.94 cw(c5626.22,4243.13) 5626.22,4261.24 ccw(c5626.22,4243.13) 5613.42,4255.94 ; 5613.42,4255.94 ccw(c5600.61,4268.74) 5618.72,4268.74 cw(c5600.61,4268.74) 5613.42,4255.94
  Top Layer w8: U7.B5@7948.43,4459.32 cw(c7948.43,4444.83) 7958.67,4455.07 cw(c7968.91,4465.32) U7.B5@7954.43,4465.32 ; U7.B5@7948.43,4465.32 v2(7968.11,4445.63) ; v2@7959.11,4445.63 ccw(c7937.38,4445.63) 7952.75,4460.99 ccw(c7968.11,4476.36) v2@7968.11,4454.63
  MidLayer2 w4: v3@5626.87,4276.21 ccw(c5628.45,4294.25) 5640.09,4280.38 ; v3@5633.69,4268.09 cw(c5651.73,4266.51) 5640.09,4280.38 ; v2(7968.11,4445.63) 7948.52,4426.04 7865.86,4426.04 7826.86,4387.04 7793.52,4387.04 7790.52,4390.04 7790.52,4417.71 7781.86,4426.37 7643.86,4426.37 7609.19,4391.71 7237.86,4391.71 7215.19,4369.04 7215.19,4287.04 7186.52,4258.37 7131.86,4258.37 7115.19,4275.04 6990.19,4275.04 6973.86,4258.71 6873.52,4258.71 6871.86,4257.04 6612.51,4257.04 6602.84,4266.71 6428.88,4266.71 6420.54,4275.04 6298.52,4275.04 6246.86,4326.71 6131.86,4326.71 6129.86,4324.71 6021.52,4324.71 6009.19,4312.37 5982.88,4312.37 5963.1,4292.6 5920,4292.6 5910,4292.6 5782.64,4292.6 5763.22,4292.6 5689.1,4292.6 5669.6,4292.6 ccw(c5669.6,4250.87) 5640.09,4280.38
DB_MEM.BUS_NBE0: U8.U19 U12.15 U16.39 | length 3312.4
  Top Layer w4: U8.U19@5606.54,4044.7 cw(c5606.54,4026.6) 5619.34,4039.4 cw(c5632.14,4052.2) U8.U19@5614.04,4052.2 ; U8.U19@5606.54,4044.86 cw(c5606.54,4027.14) 5619.07,4039.67 cw(c5631.6,4052.2) U8.U19@5613.88,4052.2 ; U8.U19@5606.54,4052.2 v3(5626.22,4032.52) ; v1@6792.81,3793.66 cw(c6776.59,3777.44) 6799.52,3777.44 cw(c6822.46,3777.44) v1@6806.24,3793.66 ; v1@6795.64,3796.49 cw(c6786.25,3787.1) 6799.52,3787.1 cw(c6812.8,3787.1) v1@6803.41,3796.49 ; v1(6799.52,3800.37) 6799.52,3736.97 6802.99,3733.5 U12.15@6845.59,3733.5 ; U12.15@6822.37,3727.85 ccw(c6808.72,3714.19) 6808.72,3733.5 ccw(c6808.72,3752.82) U12.15@6822.37,3739.16 ; v1(7102.52,4061.71) 7123.52,4082.71 7123.52,4256.37 7090.19,4289.71 7090.19,4408.37 7098.52,4416.71 7098.52,4558.37 7206.86,4666.71 7206.86,4791.71 7228.38,4813.23 U16.39@7294.41,4813.23 ; v1@7102.52,4067.21 ccw(c7102.52,4080.49) 7111.91,4071.1 ccw(c7121.3,4061.71) v1@7108.02,4061.71 ; v1@7102.52,4071.21 ccw(c7102.52,4094.14) 7118.74,4077.93 ccw(c7134.96,4061.71) v1@7112.02,4061.71 ; U16.39@7271.19,4807.57 ccw(c7257.54,4793.91) 7257.54,4813.23 ccw(c7257.54,4832.54) U16.39@7271.19,4818.88 ; 5613.42,4045.32 cw(c5600.61,4032.52) 5618.72,4032.52 ccw(c5600.61,4032.52) 5613.42,4045.32 ; 5613.42,4045.32 ccw(c5626.22,4058.13) 5626.22,4040.02 cw(c5626.22,4058.13) 5613.42,4045.32
  MidLayer2 w4: v3@5626.87,4025.05 cw(c5628.45,4007.01) 5640.09,4020.88 ; v3@5633.69,4033.17 ccw(c5651.73,4034.75) 5640.09,4020.88 ; v1@6790.02,3800.37 ccw(c6767.09,3800.37) 6783.31,3816.59 ccw(c6799.52,3832.81) v1@6799.52,3809.87 ; v1@6794.02,3800.37 ccw(c6780.75,3800.37) 6790.14,3809.76 ccw(c6799.52,3819.15) v1@6799.52,3805.87 ; v1(6799.52,3800.37) 6766.52,3833.37 6440.19,3833.37 6381.86,3891.71 6337.52,3891.71 6323.52,3877.71 6259.52,3877.71 6256.86,3875.04 6190.19,3875.04 6160.7,3845.56 6140.44,3845.56 6091,3895 6055.31,3895 6014,3936.31 6014,3950 6014,4001 6006.34,4008.66 5920,4008.66 5910,4008.66 5782.64,4008.66 5763.22,4008.66 5689.1,4008.66 5669.6,4008.66 cw(c5669.6,4050.39) 5640.09,4020.88
  Bottom Layer w4: v1(6799.52,3800.37) 6867,3800.37 6875,3808.37 6940.19,3808.37 7073.52,3941.71 7082.19,3950.37 7082.19,4041.37 v1(7102.52,4061.71) ; v1@6803.41,3796.49 cw(c6812.8,3787.1) 6812.8,3800.37 cw(c6812.8,3813.65) v1@6803.41,3804.26 ; v1@6806.24,3793.66 cw(c6822.46,3777.44) 6822.46,3800.37 cw(c6822.46,3823.31) v1@6806.24,3807.09 ; v1@7093.02,4061.71 cw(c7070.09,4061.71) 7086.31,4045.49 cw(c7102.52,4029.27) v1@7102.52,4052.21 ; v1@7097.02,4061.71 cw(c7083.75,4061.71) 7093.14,4052.32 cw(c7102.52,4042.93) v1@7102.52,4056.21
DB_MEM.BUS_NBE1: U8.A22 U12.39 U16.40 | length 4144.3
  Top Layer w4: U8.A22@5719.34,4687.43 ccw(c5706.54,4700.23) 5724.65,4700.23 ccw(c5742.75,4700.23) U8.A22@5729.95,4687.43 ; U8.A22@5719.45,4687.32 ccw(c5706.92,4699.85) 5724.65,4699.85 ccw(c5742.37,4699.85) U8.A22@5729.84,4687.32 ; U8.A22@5724.65,4682.13 5724.65,4710 5724.65,4720 5724.65,4724.74 5724.65,4745.2 5796.18,4816.74 5796.18,4831.04 5802.32,4837.17 5823.52,4858.37 5823.52,4900.04 5873.52,4950.04 5873.52,5056.71 v1(5898.52,5081.71) ; v1@5889.02,5081.71 cw(c5866.09,5081.71) 5882.31,5065.49 cw(c5898.52,5049.27) v1@5898.52,5072.21 ; v1@5893.02,5081.71 cw(c5879.75,5081.71) 5889.14,5072.32 cw(c5898.52,5062.93) v1@5898.52,5076.21 ; v1(7173.19,4779.37) 7238.54,4844.72 U16.40@7294.41,4844.72 7326.86,4844.72 ; v1@7173.19,4784.87 ccw(c7173.19,4798.15) 7182.58,4788.76 ccw(c7191.97,4779.37) v1@7178.69,4779.37 ; v1@7173.19,4788.87 ccw(c7173.19,4811.81) 7189.41,4795.59 ccw(c7205.63,4779.37) v1@7182.69,4779.37 ; U16.40@7271.19,4839.07 ccw(c7257.54,4825.41) 7257.54,4844.72 ccw(c7257.54,4864.04) U16.40@7271.19,4850.38 ; U12.39@7294.41,3702.01 7323.97,3702.01 ; U16.40@7318.64,4840.31 cw(c7326.86,4834.87) 7326.86,4844.72 ; U16.40@7318.64,4849.14 ccw(c7326.86,4854.58) 7326.86,4844.72 ; U12.39@7319.35,3698.93 cw(c7323.97,3697.01) 7323.97,3702.01 ; U12.39@7319.35,3705.08 ccw(c7323.97,3707.01) 7323.97,3702.01 ; 7323.97,3702.01 7337.94,3715.98 7349.25,3715.98 7365.19,3700.04 7365.19,3665.04 7371.86,3658.37 7433.37,3658.37 7445,3670 7445,3726.16 7478.19,3759.35 7478.19,3857.37 7435,3900.56 7435,3994.85 7468.86,4028.71 7470.19,4030.04 7470.19,4778.37 7440.19,4808.37 7363.21,4808.37 7326.86,4844.72
  MidLayer1 w4: v1(5898.52,5081.71) 5933.52,5116.71 6515.19,5116.71 6548.52,5150.04 v1(6773.52,5150.04) ; v1@5898.52,5087.21 ccw(c5898.52,5100.49) 5907.91,5091.1 ccw(c5917.3,5081.71) v1@5904.02,5081.71 ; v1@5898.52,5091.21 ccw(c5898.52,5114.14) 5914.74,5097.93 ccw(c5930.96,5081.71) v1@5908.02,5081.71 ; v1@6766.81,5143.32 ccw(c6750.59,5127.11) 6750.59,5150.04 ccw(c6750.59,5172.98) v1@6766.81,5156.76 ; v1@6769.64,5146.15 ccw(c6760.25,5136.76) 6760.25,5150.04 ccw(c6760.25,5163.32) v1@6769.64,5153.93
  Bottom Layer w4: v1@6773.52,5140.54 cw(c6773.52,5117.61) 6789.74,5133.82 cw(c6805.96,5150.04) v1@6783.02,5150.04 ; v1@6773.52,5144.54 cw(c6773.52,5131.26) 6782.91,5140.65 cw(c6792.3,5150.04) v1@6779.02,5150.04 ; v1(6773.52,5150.04) 6798.52,5125.04 6859.19,5125.04 6884.19,5100.04 6930,5100.04 6942.52,5087.52 6942.52,5069.73 7083.47,4928.78 7083.47,4869.09 v1(7173.19,4779.37) ; v1@7163.69,4779.37 ccw(c7140.76,4779.37) 7156.97,4795.59 ccw(c7173.19,4811.81) v1@7173.19,4788.87 ; v1@7167.69,4779.37 ccw(c7154.41,4779.37) 7163.8,4788.76 ccw(c7173.19,4798.15) v1@7173.19,4784.87
DB_MEM.BUS_NBE2: U8.AA25 U13.15 U17.39 | length 2817.1
  Top Layer w4: 6054.12,3799.12 6076.52,3776.71 ; 6061.52,3791.71 6076.52,3776.71 ; 6128.22,3751.78 ccw(c6153.03,3776.6) U13.15@6153.03,3741.5 ; 6135.05,3744.95 ccw(c6153.03,3762.94) U13.15@6153.03,3737.5 ; 6141.87,3738.13 ccw(c6153.03,3749.28) U13.15@6153.03,3733.5 ; U13.15@6186.37,3741.3 cw(c6190.59,3722.8) 6204.01,3736.22 ; U13.15@6187.26,3737.4 cw(c6192.49,3714.47) v1@6209.13,3731.1 ; U13.15@6188.15,3733.5 cw(c6194.4,3706.14) v1@6214.24,3725.99 ; v1@6205.69,3725.04 ccw(c6182.76,3725.04) 6198.97,3741.26 ccw(c6215.19,3757.48) v1@6215.19,3734.54 ; v1@6209.69,3725.04 ccw(c6196.41,3725.04) 6205.8,3734.43 ccw(c6215.19,3743.82) v1@6215.19,3730.54 ; v1(6215.19,3725.04) 6198.52,3741.71 U13.15@6147.19,3741.71 ; v1@6460.47,3706.76 ccw(c6444.26,3722.98) 6467.19,3722.98 ccw(c6490.13,3722.98) v1@6473.91,3706.76 ; v1@6463.3,3703.93 ccw(c6453.91,3713.32) 6467.19,3713.32 ccw(c6480.47,3713.32) v1@6471.08,3703.93 ; v1(6467.19,3700.04) 6467.19,3798.04 6456.86,3808.37 6415.19,3808.37 6390.19,3833.37 6390.19,3958.37 6373.52,3975.04 6373.52,4041.67 6406.86,4075 6406.86,4100.04 6390.52,4116.37 6390.52,4331.65 6425.52,4366.65 6425.52,4416.73 6406.86,4435.39 6406.86,4544.69 6415.19,4553.02 6415.19,4735.19 6446.58,4766.58 6493.23,4813.23 U17.39@6619.41,4813.23 6495,4813.23 ; 5855.29,3882.19 ccw(c5862.47,3889.37) 5862.47,3879.22 ; 5855.29,3882.19 ccw(c5862.47,3889.37) 5862.47,3879.22 ; 5855.29,3882.19 cw(c5867.83,3894.72) 5850.1,3894.72 ccw(c5867.83,3894.72) 5855.29,3882.19 ; 5855.29,3882.19 ccw(c5842.76,3869.66) 5842.76,3887.38 cw(c5842.76,3869.66) 5855.29,3882.19 ; 5862.47,3879.22 5910,3879.22 5920,3879.22 5974.01,3879.22 6076.52,3776.71 ; 6076.52,3776.71 6078.19,3775.04 ; 6076.52,3776.71 6078.19,3775.04 ; 6078.19,3775.04 6090,3775 6105,3775 6146.5,3733.5 U13.15@6155.4,3733.5 ; U13.15@6147.19,3741.71 U13.15@6155.4,3733.5 ; U13.15@6147.19,3741.71 U13.15@6155.4,3733.5 ; U13.15@6155.4,3733.5 U13.15@6170.59,3733.5 U13.15@6155.4,3733.5 ; 6582.54,4813.23 cw(c6582.54,4793.91) 6596.19,4807.57 ccw(c6582.54,4793.91) 6582.54,4813.23 ; 6582.54,4813.23 ccw(c6582.54,4832.54) 6596.19,4818.88 cw(c6582.54,4832.54) 6582.54,4813.23
  Bottom Layer w4: v1(6215.19,3725.04) 6240.19,3750.04 6310,3750.04 6310.5,3750.54 6348.02,3750.54 6365.19,3733.37 6433.86,3733.37 v1(6467.19,3700.04) ; v1@6215.19,3730.54 ccw(c6215.19,3743.82) 6224.58,3734.43 ccw(c6233.97,3725.04) v1@6220.69,3725.04 ; v1@6215.19,3734.54 ccw(c6215.19,3757.48) 6231.41,3741.26 ccw(c6247.63,3725.04) v1@6224.69,3725.04 ; v1@6457.69,3700.04 ccw(c6434.76,3700.04) 6450.97,3716.26 ccw(c6467.19,3732.48) v1@6467.19,3709.54 ; v1@6461.69,3700.04 ccw(c6448.41,3700.04) 6457.8,3709.43 ccw(c6467.19,3718.82) v1@6467.19,3705.54
DB_MEM.BUS_NBE3: U8.V25 U13.39 U17.40 | length 2854.6
  Top Layer w4: U8.V25@5842.76,4005.49 cw(c5842.76,3987.77) 5855.29,4000.3 ; U8.V25@5850.1,4012.83 ccw(c5867.83,4012.83) 5855.29,4000.3 ; 6056.33,3992.23 ccw(c6075,4010.9) v1@6075,3984.5 ; 6059.8,3988.77 cw(c6046.03,3975) v1@6065.5,3975 ; 6063.16,3985.4 ccw(c6075,3997.24) v1@6075,3980.5 ; v1(6075,3975) 6073.56,3975 6047.03,4001.54 6034,4001.54 6021.51,4001.54 6017.31,3997.33 5970.79,3997.33 5960,3997.33 5924.74,3997.33 5920,3997.33 5910,3997.33 5862.47,3997.33 cw(c5862.47,4007.48) 5855.29,4000.3 ; U13.39@6619.41,3702.01 6646.97,3702.01 6661.67,3716.71 ; U17.40@6619.41,4844.72 6670.51,4844.72 6765.19,4750.04 6765.19,4720.37 6790.19,4695.37 6790.19,4653.37 6806.86,4636.71 6806.86,4475.04 6781.86,4450.04 6781.86,4383.37 6773.52,4375.04 6773.52,4325.04 6738.86,4290.37 6738.86,4257.04 6706.86,4225.04 6706.86,4200.04 6731.86,4175.04 6731.86,4115.37 6715.19,4098.71 v1(6715.19,3938.71) 6715.19,3852.37 6725.86,3841.71 6754.19,3841.71 6765.19,3830.71 6765.19,3711.04 6754.19,3700.04 6724.86,3700.04 6708.19,3716.71 6661.67,3716.71 ; U13.39@6636.97,3702.01 ccw(c6640.17,3717.29) 6651.21,3706.25 ; U13.39@6637.79,3705.92 ccw(c6641.98,3725.94) 6656.44,3711.48 ; U13.39@6638.61,3709.84 ccw(c6643.79,3734.59) 6661.67,3716.71 ; U17.40@6642.63,4839.07 cw(c6656.28,4825.41) 6656.28,4844.72 cw(c6656.28,4864.04) U17.40@6642.63,4850.38 ; v1@6708.47,3931.99 cw(c6692.26,3915.77) 6715.19,3915.77 cw(c6738.13,3915.77) v1@6721.91,3931.99 ; v1@6708.47,3945.43 ccw(c6692.26,3961.64) 6715.19,3961.64 ccw(c6738.13,3961.64) v1@6721.91,3945.43 ; v1@6711.3,3934.82 cw(c6701.91,3925.43) 6715.19,3925.43 cw(c6728.47,3925.43) v1@6719.08,3934.82 ; v1@6711.3,3942.6 ccw(c6701.91,3951.99) 6715.19,3951.99 ccw(c6728.47,3951.99) v1@6719.08,3942.6
  MidLayer2 w4: v1(6075,3975) 6100,4000 6141.9,4000 6155.53,3986.37 ; v1@6075,3980.5 ccw(c6075,3993.78) 6084.39,3984.39 ccw(c6093.78,3975) v1@6080.5,3975 ; v1@6075,3984.5 ccw(c6075,4007.43) 6091.22,3991.22 ccw(c6107.43,3975) v1@6084.5,3975 ; 6141.9,4000 6155.53,3986.37 ; v1@6705.69,3938.71 ccw(c6682.76,3938.71) 6698.97,3954.93 ccw(c6715.19,3971.14) v1@6715.19,3948.21 ; v1@6709.69,3938.71 ccw(c6696.41,3938.71) 6705.8,3948.1 ccw(c6715.19,3957.49) v1@6715.19,3944.21 ; v1(6715.19,3938.71) 6687.19,3966.71 6384.84,3966.71 6357.17,3994.37 6265.19,3994.37 6229.19,3958.37 6183.52,3958.37 6155.53,3986.37
DB_MEM.BUS_NOE: U7.G2 U8.AD11 U16.41 U17.41 U61.107 | length 9153
  Top Layer w4: 5267.71,3651.25 5267.71,3654.46 ; U8.AD11@5284.23,3776.61 cw(c5266.51,3776.61) 5279.04,3764.08 ; U8.AD11@5291.57,3769.27 ccw(c5291.57,3751.55) 5279.04,3764.08 ; 5338.93,3316.45 cw(c5356.86,3298.53) v1@5356.86,3323.87 ; 5341.35,3318.86 ccw(c5326.84,3333.37) v1@5347.36,3333.37 ; 5345.76,3323.28 cw(c5356.86,3312.18) v1@5356.86,3327.87 ; 5348.18,3325.69 ccw(c5340.49,3333.37) v1@5351.36,3333.37 ; v1(5356.86,3333.37) 5355.86,3333.37 5322,3299.52 5322,3256.85 5298.52,3233.37 5265.19,3233.37 5232.19,3266.37 5232.19,3422.19 5238.02,3428.02 5238.02,3552.62 5267.71,3582.31 5267.71,3654.46 ; v1(5398.52,2678.71) 5425.18,2705.36 U61.107@5516.83,2705.36 ; v1@5398.52,2684.21 ccw(c5398.52,2697.49) 5407.91,2688.1 ccw(c5417.3,2678.71) v1@5404.02,2678.71 ; v1@5398.52,2688.21 ccw(c5398.52,2711.14) 5414.74,2694.93 ccw(c5430.96,2678.71) v1@5408.02,2678.71 ; U61.107@5500.81,2702.53 ccw(c5493.98,2695.7) 5493.98,2705.36 ccw(c5493.98,2715.02) U61.107@5500.81,2708.19 ; U17.41@6629.04,4876.22 cw(c6629.04,4830.7) v1@6661.29,4862.83 ; U17.41@6638.67,4876.22 cw(c6638.67,4840.29) v1@6664.13,4865.65 ; U17.41@6642.75,4870.69 cw(c6655.68,4858.34) 6655.68,4876.22 ; U17.41@6642.75,4881.75 ccw(c6655.68,4894.1) 6655.68,4876.22 ; 6648.31,4876.22 cw(c6648.31,4849.89) v1@6666.96,4868.47 ; v1@6658.46,4860 ccw(c6619.41,4821.1) U17.41@6619.41,4876.22 6655.68,4876.22 ; v1(6665.19,4866.71) 6655.68,4876.22 ; v1(7185.52,4833.37) 7228.37,4876.22 U16.41@7294.41,4876.22 7346.86,4876.22 7356.86,4866.22 v1(7356.86,4840.71) ; v1@7185.52,4838.87 ccw(c7185.52,4852.15) 7194.91,4842.76 ccw(c7204.3,4833.37) v1@7191.02,4833.37 ; v1@7185.52,4842.87 ccw(c7185.52,4865.81) 7201.74,4849.59 ccw(c7217.96,4833.37) v1@7195.02,4833.37 ; U16.41@7271.19,4870.56 ccw(c7257.54,4856.91) 7257.54,4876.22 ccw(c7257.54,4895.53) U16.41@7271.19,4881.88 ; U16.41@7317.63,4870.56 cw(c7331.28,4856.91) 7331.28,4876.22 cw(c7331.28,4895.53) U16.41@7317.63,4881.88 ; v1@7350.14,4847.43 ccw(c7333.92,4863.64) 7356.86,4863.64 ccw(c7379.79,4863.64) v1@7363.57,4847.43 ; v1@7352.97,4844.6 ccw(c7343.58,4853.99) 7356.86,4853.99 ccw(c7370.14,4853.99) v1@7360.75,4844.6 ; v1@7541.81,3626.66 cw(c7525.59,3610.44) 7548.52,3610.44 cw(c7571.46,3610.44) v1@7555.24,3626.66 ; v1@7544.64,3629.49 cw(c7535.25,3620.1) 7548.52,3620.1 cw(c7561.8,3620.1) v1@7552.41,3629.49 ; v1(7548.52,3633.37) 7548.52,3523.04 7631.86,3439.71 7631.86,3270.37 7690.19,3212.04 7690.19,2984.71 v1(7655.52,2950.04) ; v1@7655.52,2955.54 ccw(c7655.52,2968.82) 7664.91,2959.43 ccw(c7674.3,2950.04) v1@7661.02,2950.04 ; v1@7655.52,2959.54 ccw(c7655.52,2982.48) 7671.74,2966.26 ccw(c7687.96,2950.04) v1@7665.02,2950.04 ; 5267.71,3654.46 5267.71,3655.26 5267.71,3659.75 ; 5267.71,3654.46 5267.71,3659.75 ; 5267.71,3659.75 5267.71,3660 5267.71,3670 5267.71,3736.73 cw(c5306.39,3736.73) 5279.04,3764.08
  Top Layer w8: v2@7731.89,4594.11 cw(c7731.89,4572.38) 7747.25,4587.75 cw(c7762.62,4603.11) v2@7740.89,4603.11 ; v2(7731.89,4603.11) U7.G2@7751.58,4583.43 ; U7.G2@7745.58,4583.43 ccw(c7731.09,4583.43) 7741.33,4593.67 ccw(c7751.58,4603.91) U7.G2@7751.58,4589.43
  MidLayer1 w4: v1@5356.86,3323.87 cw(c5356.86,3300.94) 5373.07,3317.16 cw(c5389.29,3333.37) v1@5366.36,3333.37 ; v1@5356.86,3327.87 cw(c5356.86,3314.6) 5366.25,3323.99 cw(c5375.64,3333.37) v1@5362.36,3333.37 ; v1(5356.86,3333.37) 5440.19,3250.04 5440.19,3190 5431.86,3181.67 5431.86,3160 5431.86,2970.21 5428.15,2966.5 5427.81,2966.5 5403.5,2942.19 5403.5,2941.85 5381.52,2919.87 5381.52,2695.71 v1(5398.52,2678.71) ; v1@5389.02,2678.71 ccw(c5366.09,2678.71) 5382.31,2694.93 ccw(c5398.52,2711.14) v1@5398.52,2688.21 ; v1@5393.02,2678.71 ccw(c5379.75,2678.71) 5389.14,2688.1 ccw(c5398.52,2697.49) v1@5398.52,2684.21 ; v1@7539.02,3633.37 ccw(c7516.09,3633.37) 7532.31,3649.59 ccw(c7548.52,3665.81) v1@7548.52,3642.87 ; v1@7543.02,3633.37 ccw(c7529.75,3633.37) 7539.14,3642.76 ccw(c7548.52,3652.15) v1@7548.52,3638.87 ; v1(7548.52,3633.37) 7523.52,3658.37 7523.52,3745 7506.86,3761.67 7506.86,3916.71 7506.86,4456.86 7631.86,4581.86 7631.86,4606.71 7648.52,4623.37 7711.63,4623.37 v2(7731.89,4603.11) ; v2@7720.89,4603.11 ccw(c7694.33,4603.11) 7713.11,4621.89 ccw(c7731.89,4640.67) v2@7731.89,4614.11 ; v2@7724.89,4603.11 ccw(c7707.99,4603.11) 7719.94,4615.06 ccw(c7731.89,4627.01) v2@7731.89,4610.11
  MidLayer2 w4: v1@6655.69,4866.71 cw(c6632.76,4866.71) 6648.97,4850.49 cw(c6665.19,4834.27) v1@6665.19,4857.21 ; v1@6659.69,4866.71 cw(c6646.41,4866.71) 6655.8,4857.32 cw(c6665.19,4847.93) v1@6665.19,4861.21 ; v1(6665.19,4866.71) 6640.19,4841.71 6640.19,4809.37 6674.52,4775.04 6691.19,4775.04 6724.52,4808.37 6786.52,4808.37 6811.52,4783.37 7135.52,4783.37 v1(7185.52,4833.37) ; v1@7176.02,4833.37 cw(c7153.09,4833.37) 7169.31,4817.16 cw(c7185.52,4800.94) v1@7185.52,4823.87 ; v1@7180.02,4833.37 cw(c7166.75,4833.37) 7176.14,4823.99 cw(c7185.52,4814.6) v1@7185.52,4827.87
  Bottom Layer w4: v1(5398.52,2678.71) 5411.52,2691.71 5556.86,2691.71 5573.52,2708.37 5573.52,2725.04 5581.86,2733.37 5721.86,2733.37 5723.52,2731.71 5723.52,2691.71 5714.19,2682.37 5714.19,2642.37 5723.19,2633.37 5758.52,2633.37 5814.19,2577.71 6382.17,2577.71 6392.17,2567.71 6469.17,2567.71 6509.84,2608.37 6688.52,2608.37 6698.52,2618.37 6960.25,2618.37 6966.92,2625.04 7115.19,2625.04 7381.86,2891.71 7506.86,2891.71 7565.19,2950.04 v1(7655.52,2950.04) ; v1@7350.14,4847.43 ccw(c7333.92,4863.64) 7356.86,4863.64 ccw(c7379.79,4863.64) v1@7363.57,4847.43 ; v1@7352.97,4844.6 ccw(c7343.58,4853.99) 7356.86,4853.99 ccw(c7370.14,4853.99) v1@7360.75,4844.6 ; v1(7356.86,4840.71) 7356.86,4881.86 7373.34,4898.34 7373.34,4918.34 7520,5065 7616.9,5065 7673.19,5008.71 7673.19,4631.37 7682.19,4622.37 7712.63,4622.37 v2(7731.89,4603.11) ; v1@7648.81,2943.32 ccw(c7632.59,2927.11) 7632.59,2950.04 ccw(c7632.59,2972.98) v1@7648.81,2956.76 ; v1@7651.64,2946.15 ccw(c7642.25,2936.76) 7642.25,2950.04 ccw(c7642.25,2963.32) v1@7651.64,2953.93 ; v2@7720.89,4603.11 ccw(c7694.33,4603.11) 7713.11,4621.89 ccw(c7731.89,4640.67) v2@7731.89,4614.11 ; v2@7724.89,4603.11 ccw(c7707.99,4603.11) 7719.94,4615.06 ccw(c7731.89,4627.01) v2@7731.89,4610.11
DB_MEM.BUS_NWE: U7.A5 U8.M3 U12.16 U13.16 U16.17 U17.17 U61.108 | length 13659.1
  Top Layer w4: v1@4684.86,4354.21 cw(c4684.86,4331.27) 4701.07,4347.49 cw(c4717.29,4363.71) v1@4694.36,4363.71 ; v1@4684.86,4358.21 cw(c4684.86,4344.93) 4694.25,4354.32 cw(c4703.64,4363.71) v1@4690.36,4363.71 ; v1(4684.86,4363.71) 4774.02,4274.54 4820,4274.54 4821.62,4272.92 4855.26,4272.92 ; 4848.52,4272.92 4851.26,4272.92 4855.26,4272.92 ; U8.M3@4969.27,4249.06 ccw(c4951.55,4249.06) 4964.08,4261.59 ; U8.M3@4976.61,4256.4 cw(c4976.61,4274.12) 4964.08,4261.59 ; U61.108@5516.83,2685.68 5548.19,2685.68 5583.83,2650.04 5609.52,2650.04 5623.52,2636.04 5623.52,2476.04 5699.52,2400.04 6140.19,2400.04 6223.52,2316.71 6286.19,2316.71 6323.52,2279.37 6494.52,2279.37 6531.86,2316.71 6531.86,2458.37 6548.52,2475.04 6571.52,2475.04 6581.86,2485.37 6581.86,2641.86 6606.71,2666.71 6874.52,2666.71 v1(6924.52,2716.71) ; U61.108@5532.85,2682.85 cw(c5539.68,2676.02) 5539.68,2685.68 cw(c5539.68,2695.33) U61.108@5532.85,2688.5 ; v1@6127.52,4480.54 cw(c6127.52,4457.61) 6143.74,4473.82 cw(c6159.96,4490.04) v1@6137.02,4490.04 ; v1@6127.52,4484.54 cw(c6127.52,4471.26) 6136.91,4480.65 cw(c6146.3,4490.04) v1@6133.02,4490.04 ; v1(6127.52,4490.04) 6150.79,4466.77 U17.17@6170.59,4466.77 U17.17@6173.52,4466.77 ; v1@6135.55,4482.01 ccw(c6153.03,4499.49) U17.17@6153.03,4474.77 ; 6140.96,4476.61 cw(c6131.12,4466.77) U17.17@6145.03,4466.77 ; 6142.38,4475.18 ccw(c6153.03,4485.83) U17.17@6153.03,4470.77 ; U13.16@6170.59,3702.01 6204.89,3702.01 ; U13.16@6194.37,3696.98 cw(c6204.89,3688.49) 6204.89,3702.01 ; U13.16@6194.37,3707.03 ccw(c6204.89,3715.52) 6204.89,3702.01 ; v1@6330.69,3733.04 cw(c6307.76,3733.04) 6323.97,3716.82 cw(c6340.19,3700.61) v1@6340.19,3723.54 ; v1@6334.69,3733.04 cw(c6321.41,3733.04) 6330.8,3723.65 cw(c6340.19,3714.26) v1@6340.19,3727.54 ; v1(6340.19,3733.04) 6298.86,3691.71 6215.19,3691.71 6204.89,3702.01 ; U12.16@6845.59,3702.01 6892.99,3702.01 6898.52,3696.48 v1(6898.52,3666.71) ; U16.17@6845.59,4466.77 6875.59,4466.77 ; U12.16@6868.81,3696.35 cw(c6882.46,3682.69) 6882.46,3702.01 cw(c6882.46,3721.32) U12.16@6868.81,3707.66 ; U16.17@6870.43,4463.45 cw(c6875.59,4461.1) 6875.59,4466.77 ; U16.17@6870.43,4470.09 ccw(c6875.59,4472.44) 6875.59,4466.77 ; v1@6890.18,4469.16 ccw(c6882.52,4464.98) 6882.52,4473.71 ; v1@6890.18,4478.26 cw(c6882.52,4482.43) 6882.52,4473.71 ; v1@6891.81,3673.43 ccw(c6875.59,3689.64) 6898.52,3689.64 ccw(c6921.46,3689.64) v1@6905.24,3673.43 ; v1@6894.64,3670.6 ccw(c6885.25,3679.99) 6898.52,3679.99 ccw(c6911.8,3679.99) v1@6902.41,3670.6 ; v1(6898.52,4473.71) 6882.52,4473.71 ; v1@6915.02,2716.71 cw(c6892.09,2716.71) 6908.31,2700.49 cw(c6924.52,2684.27) v1@6924.52,2707.21 ; v1@6919.02,2716.71 cw(c6905.75,2716.71) 6915.14,2707.32 cw(c6924.52,2697.93) v1@6924.52,2711.21 ; 4855.26,4272.92 4860,4272.92 4870,4272.92 4936.73,4272.92 cw(c4936.73,4234.24) 4964.08,4261.59 ; 6875.59,4466.77 6882.52,4473.71
  Top Layer w8: U7.A5@7987.8,4459.32 cw(c7987.8,4444.83) 7998.04,4455.07 cw(c8008.28,4465.32) U7.A5@7993.8,4465.32 ; U7.A5@7987.8,4465.32 v2(8007.48,4445.63) ; v2@7998.48,4445.63 ccw(c7976.75,4445.63) 7992.12,4460.99 ccw(c8007.48,4476.36) v2@8007.48,4454.63
  MidLayer1 w4: v1(6127.52,4490.04) 6162.52,4525.04 6265.19,4525.04 6306.86,4566.71 6373.52,4566.71 6389.19,4551.04 6568.96,4551.04 6577.96,4542.04 6830.19,4542.04 v1(6898.52,4473.71) 6966.52,4541.71 6990.19,4541.71 7006.86,4558.37 7006.86,4633.37 6948.52,4691.71 6865.19,4691.71 6856.86,4683.37 6773.52,4683.37 6756.86,4700.04 v1(6681.86,4700.04) ; v1@6127.52,4495.54 ccw(c6127.52,4508.82) 6136.91,4499.43 ccw(c6146.3,4490.04) v1@6133.02,4490.04 ; v1@6127.52,4499.54 ccw(c6127.52,4522.48) 6143.74,4506.26 ccw(c6159.96,4490.04) v1@6137.02,4490.04 ; v1@6685.75,4696.15 cw(c6695.14,4686.76) 6695.14,4700.04 cw(c6695.14,4713.32) v1@6685.75,4703.93 ; v1@6688.57,4693.32 cw(c6704.79,4677.11) 6704.79,4700.04 cw(c6704.79,4722.98) v1@6688.57,4706.76 ; v1@6889.02,4473.71 ccw(c6866.09,4473.71) 6882.31,4489.93 ccw(c6898.52,4506.14) 6898.52,4483.21 ccw(c6898.52,4506.14) 6914.74,4489.93 ccw(c6930.96,4473.71) v1@6908.02,4473.71 ; v1@6893.02,4473.71 ccw(c6879.75,4473.71) 6889.14,4483.1 ccw(c6898.52,4492.49) 6898.52,4479.21 ccw(c6898.52,4492.49) 6907.91,4483.1 ccw(c6917.3,4473.71) v1@6904.02,4473.71 ; v1(6898.52,3666.71) 6981.86,3750.04 6981.86,3872.06 7065,3955.2 ; v1@6898.52,3672.21 ccw(c6898.52,3685.49) 6907.91,3676.1 ccw(c6917.3,3666.71) v1@6904.02,3666.71 ; v1@6898.52,3676.21 ccw(c6898.52,3699.14) 6914.74,3682.93 ccw(c6930.96,3666.71) v1@6908.02,3666.71 ; v1@6941.81,4740.09 ccw(c6925.59,4756.31) 6948.52,4756.31 ccw(c6971.46,4756.31) v1@6955.24,4740.09 ; v1@6944.64,4737.26 ccw(c6935.25,4746.65) 6948.52,4746.65 ccw(c6961.8,4746.65) v1@6952.41,4737.26 ; v1(6948.52,4733.37) 6948.52,4783.37 6965.19,4800.04 7189.52,4800.04 7198.52,4791.04 7198.52,4633.37 7115.19,4550.04 7115.19,4475.04 7140.19,4450.04 7140.19,4314.37 7131.86,4306.04 7131.86,4191.71 7065.52,4125.37 7065.52,3955.73
  MidLayer2 w4: v1(4684.86,4363.71) 4669.19,4379.37 4669.19,4580.37 4656.19,4593.37 4656.19,4721.39 4756.86,4822.06 4756.86,5058.37 4856.86,5158.37 5115.19,5158.37 5177.56,5096 5322.15,5096 ; 5330.01,5103.86 5322.15,5096 ; v1@6340.19,3723.54 cw(c6340.19,3700.61) 6356.41,3716.82 cw(c6372.63,3733.04) v1@6349.69,3733.04 ; v1@6340.19,3727.54 cw(c6340.19,3714.26) 6349.58,3723.65 cw(c6358.97,3733.04) v1@6345.69,3733.04 ; v1(6340.19,3733.04) 6356.52,3716.71 6406.86,3716.71 6451.19,3672.37 6729.19,3672.37 6781.86,3725.04 6840.19,3725.04 v1(6898.52,3666.71) 7015.19,3550.04 7015.19,3166.71 6942.19,3093.71 6942.19,3023.04 6973.52,2991.71 6973.52,2765.71 v1(6924.52,2716.71) ; v1@6672.36,4700.04 ccw(c6649.42,4700.04) 6665.64,4716.26 ccw(c6681.86,4732.48) v1@6681.86,4709.54 ; v1@6676.36,4700.04 ccw(c6663.08,4700.04) 6672.47,4709.43 ccw(c6681.86,4718.82) v1@6681.86,4705.54 ; v1(6681.86,4700.04) 6630.02,4751.87 6630.02,5151.74 6581.73,5200.04 5672.21,5200.04 5642.88,5229.37 5455.52,5229.37 5322.15,5096 ; v1@6889.02,3666.71 ccw(c6866.09,3666.71) 6882.31,3682.93 ccw(c6898.52,3699.14) v1@6898.52,3676.21 ; v1@6893.02,3666.71 ccw(c6879.75,3666.71) 6889.14,3676.1 ccw(c6898.52,3685.49) v1@6898.52,3672.21 ; v1@6898.52,3657.21 cw(c6898.52,3634.27) 6914.74,3650.49 cw(c6930.96,3666.71) v1@6908.02,3666.71 ; v1@6898.52,3661.21 cw(c6898.52,3647.93) 6907.91,3657.32 cw(c6917.3,3666.71) v1@6904.02,3666.71 ; v1(6898.52,4473.71) 6913.86,4458.37 6964.19,4458.37 6973.52,4467.71 6973.52,4500 6973.52,4508.37 6973.52,4522.06 6984.84,4533.37 6998.52,4533.37 7020,4533.37 7153.19,4533.37 7211.52,4475.04 7269.19,4475.04 7278.19,4484.04 7969.07,4484.04 ; v1@6924.52,2722.21 ccw(c6924.52,2735.49) 6933.91,2726.1 ccw(c6943.3,2716.71) v1@6930.02,2716.71 ; v1@6924.52,2726.21 ccw(c6924.52,2749.14) 6940.74,2732.93 ccw(c6956.96,2716.71) v1@6934.02,2716.71 ; v2@7996.48,4445.63 ccw(c7969.92,4445.63) 7988.7,4464.41 ccw(c8007.48,4483.19) v2@8007.48,4456.63 ; v2@8000.48,4445.63 ccw(c7983.58,4445.63) 7995.53,4457.58 ccw(c8007.48,4469.53) v2@8007.48,4452.63 ; 7969.07,4484.04 7969.74,4483.37 ; 7969.07,4484.04 7977.05,4476.06 ; 7969.07,4484.04 7973.92,4479.19 ; 7969.74,4483.37 v2(8007.48,4445.63) ; 7969.74,4483.37 7973.92,4479.19 ; 7973.92,4479.19 7996.56,4456.55 ; 7973.92,4479.19 7977.05,4476.06 ; 7977.05,4476.06 7977.76,4475.35 7980.19,4472.92 7996.56,4456.55 ; 7996.56,4456.55 v2(8007.48,4445.63) ; 7996.56,4456.55 v2(8007.48,4445.63)
  Bottom Layer w4: v1(6898.52,4473.71) 6948.52,4523.71 v1(6948.52,4733.37) ; v1@6898.52,4479.21 ccw(c6898.52,4492.49) 6907.91,4483.1 ccw(c6917.3,4473.71) v1@6904.02,4473.71 ; v1@6898.52,4483.21 ccw(c6898.52,4506.14) 6914.74,4489.93 ccw(c6930.96,4473.71) v1@6908.02,4473.71 ; v1@6941.81,4726.66 cw(c6925.59,4710.44) 6948.52,4710.44 cw(c6971.46,4710.44) v1@6955.24,4726.66 ; v1@6944.64,4729.49 cw(c6935.25,4720.1) 6948.52,4720.1 cw(c6961.8,4720.1) v1@6952.41,4729.49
